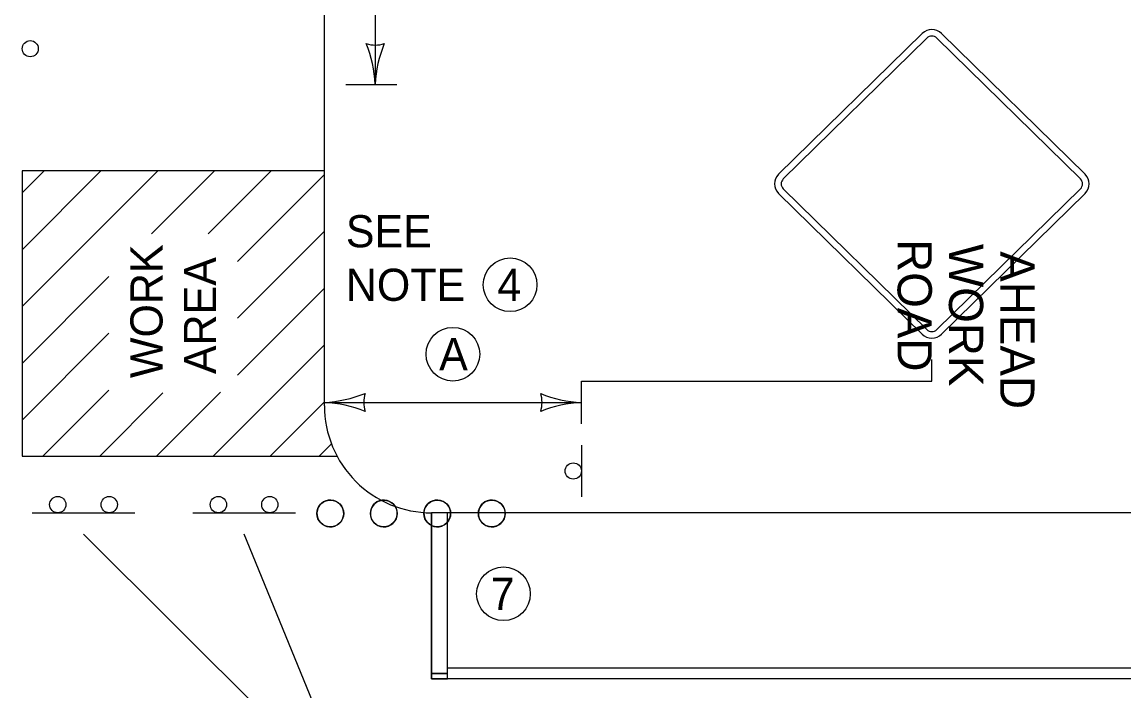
# Model space of a CAD drawing. Extents: x 49991.4 to 50021, y 49987.6 to 50011.4.
# Drawn here: x 50001.903 to 50003.961, y 49993.408 to 49994.657 of the extents above; entities that cross this region are included whole.
import ezdxf

# ---------------------------------------------------------------- set-up
doc = ezdxf.new("R2010")
doc.units = 0
for name, color, linetype in [('Level 1', 7, 'Continuous'), ('Level 2', 7, 'Continuous'), ('Level 3', 7, 'Continuous')]:
    doc.layers.add(name, color=color, linetype=linetype)

# ---------------------------------------------------------------- blocks, each defined once
blk = doc.blocks.new('ARR')
at = {"layer": 'Level 3'}
for centre, radius, start, end in [((1.53, 37.02), 37.05, 247.456, 267.6395), ((-21.37, 0), 9.13, 342.1388, 17.8612), ((1.92, -38.79), 38.83, 92.8273, 112.0772)]:
    blk.add_arc(centre, radius, start, end, dxfattribs=at)

msp = doc.modelspace()

# ---------------------------------------------------------------- linework, layer by layer
at = {"layer": 'Level 1'}
for p, q in [((50002.4673, 49993.9404), (50002.4673, 49996.0633)), ((50003.3156, 49994.3726), (50003.5839, 49994.6354)), ((50003.6198, 49994.6354), (50003.888, 49994.3726)), ((50003.3242, 49994.3638), (50003.5925, 49994.6266)), ((50003.6112, 49994.6266), (50003.8794, 49994.3638)), ((50002.4673, 49994.3789), (50001.9025, 49994.3789)), ((50001.9025, 49994.3789), (50001.9025, 49993.8464)), ((50001.9025, 49994.3377), (50001.9438, 49994.3789)), ((50001.9025, 49994.2316), (50002.0498, 49994.3789)), ((50001.9025, 49994.1255), (50002.1559, 49994.3789)), ((50002.1441, 49994.2611), (50002.262, 49994.3789)), ((50002.2502, 49994.2611), (50002.368, 49994.3789)), ((50002.3049, 49994.2097), (50002.4673, 49994.3721)), ((50003.5925, 49994.0826), (50003.3242, 49994.3454)), ((50003.8794, 49994.3454), (50003.6112, 49994.0826)), ((50003.5839, 49994.0738), (50003.3156, 49994.3366)), ((50003.888, 49994.3366), (50003.6198, 49994.0738)), ((50002.3049, 49994.1037), (50002.4673, 49994.2661)), ((50001.9025, 49994.0195), (50002.0649, 49994.1819)), ((50002.3049, 49993.9976), (50002.4673, 49994.16)), ((50001.9025, 49993.9134), (50002.0649, 49994.0758)), ((50002.2598, 49993.8464), (50002.4673, 49994.0539)), ((50001.9416, 49993.8464), (50002.0649, 49993.9697)), ((50002.0477, 49993.8464), (50002.1655, 49993.9643)), ((50002.1537, 49993.8464), (50002.2732, 49993.9659)), ((50002.3659, 49993.8464), (50002.4673, 49993.9479)), ((50002.4578, 49993.8464), (50002.4804, 49993.8691)), ((50002.9473, 49993.8665), (50002.9473, 49993.7705)), ((50001.9025, 49993.8464), (50002.4908, 49993.8464)), ((50001.9213, 49993.7405), (50002.0173, 49993.7405)), ((50002.0173, 49993.7405), (50002.1133, 49993.7405)), ((50002.2213, 49993.7405), (50002.3173, 49993.7405)), ((50002.3173, 49993.7405), (50002.4133, 49993.7405)), ((50004.4673, 49993.7404), (50002.6673, 49993.7404)), ((50002.6673, 49993.4304), (50002.6673, 49993.7404)), ((50002.6973, 49993.4304), (50002.6973, 49993.7404)), ((50002.6973, 49993.4405), (50002.6673, 49993.4405)), ((50004.4673, 49993.4504), (50002.6973, 49993.4504)), ((50004.4673, 49993.4304), (50002.6673, 49993.4304))]:
    msp.add_line(p, q, dxfattribs=at)
for points in [[(50002.6973, 49993.7404), (50002.6673, 49993.7404), (50002.6673, 49993.4405), (50002.6973, 49993.4405), (50002.6973, 49993.7404)], [(50002.6673, 49993.4405), (50002.6673, 49993.4304), (50002.6973, 49993.4304), (50002.6973, 49993.4405), (50002.6673, 49993.4405)]]:
    msp.add_lwpolyline(points, dxfattribs=at)
for centre, radius in [((50001.9179, 49994.607), 0.015), ((50002.9321, 49993.8185), 0.0152), ((50001.9693, 49993.7557), 0.0152), ((50002.0653, 49993.7557), 0.0152), ((50002.2693, 49993.7557), 0.0152), ((50002.3653, 49993.7557), 0.0152), ((50002.4783, 49993.7392), 0.025), ((50002.5782, 49993.7392), 0.025), ((50002.6781, 49993.7392), 0.025), ((50002.7799, 49993.7392), 0.025)]:
    msp.add_circle(centre, radius, dxfattribs=at)
for centre, radius, start, end in [((50002.6673, 49993.9404), 0.2, 180, 270.0006), ((50002.4783, 49993.7392), 0.025, 357.0759, 177.0759), ((50002.5782, 49993.7392), 0.025, 357.0759, 177.0759), ((50002.6781, 49993.7392), 0.025, 357.0759, 177.0759), ((50002.7799, 49993.7392), 0.025, 357.0759, 177.0759), ((50002.4783, 49993.7392), 0.025, 177.0759, 357.0759), ((50002.5782, 49993.7392), 0.025, 177.0759, 357.0759), ((50002.6781, 49993.7392), 0.025, 177.0759, 357.0759), ((50002.7799, 49993.7392), 0.025, 177.0759, 357.0759)]:
    msp.add_arc(centre, radius, start, end, dxfattribs=at)
for centre, major_axis, ratio, start_param, end_param in [((50003.6019, 49994.6175), (-0.0255, 0), 0.98963, 3.926991, 5.497787), ((50003.6019, 49994.6175), (-0.0132, 0), 0.98, 3.926991, 5.497787), ((50003.3337, 49994.3546), (-0.0255, 0), 0.98963, 5.497787, 7.068583), ((50003.8701, 49994.3546), (0.0255, 0), 0.98963, 5.497795, 7.068583), ((50003.3337, 49994.3546), (-0.0132, 0), 0.98, 5.497787, 7.068583), ((50003.8701, 49994.3546), (0.0132, 0), 0.98, 5.497795, 7.068583), ((50003.6019, 49994.0918), (-0.0132, 0), 0.98, 0.785394, 2.356194), ((50003.6019, 49994.0918), (-0.0255, 0), 0.98963, 0.785394, 2.356194)]:
    msp.add_ellipse(centre, major_axis=major_axis, ratio=ratio, start_param=start_param, end_param=end_param, dxfattribs=at)
at = {"layer": 'Level 2'}
for centre in [(50002.8142, 49994.1662), (50002.7073, 49994.0366), (50002.8017, 49993.5892)]:
    msp.add_circle(centre, 0.0501, dxfattribs=at)
at = {"layer": 'Level 3'}
for p, q in [((50002.5623, 49995.2104), (50002.5623, 49994.5404)), ((50002.5073, 49994.5404), (50002.6023, 49994.5404)), ((50002.9473, 49993.9065), (50002.9473, 49993.9865)), ((50002.4673, 49993.9465), (50002.9473, 49993.9465)), ((50002.5242, 49993.1959), (50002.0173, 49993.7005)), ((50002.5242, 49993.1959), (50002.3173, 49993.7005))]:
    msp.add_line(p, q, dxfattribs=at)
msp.add_lwpolyline([(50002.9473, 49993.9865), (50003.6019, 49993.9865), (50003.6019, 49994.0265)], dxfattribs=at)

# ---------------------------------------------------------------- block references
at = {"layer": 'Level 2', "xscale": 0.006, "yscale": 0.006}
for p, rotation in [((50002.4673, 49993.9465), -179.9999999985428), ((50002.9473, 49993.9465), 1.457212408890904e-09)]:
    msp.add_blockref('ARR', p, dxfattribs=dict(at, rotation=rotation))
at = {"layer": 'Level 3', "xscale": 0.006, "yscale": 0.006, "rotation": -90}
msp.add_blockref('ARR', (50002.5623, 49994.5404), dxfattribs=at)

# ---------------------------------------------------------------- texts
at = {"layer": 'Level 1'}
for s, p in [('ROAD', (50003.5379, 49994.2514)), ('WORK', (50003.6338, 49994.2424)), ('AHEAD', (50003.7297, 49994.2288))]:
    msp.add_text(s, height=0.06395, rotation=270, dxfattribs=at).set_placement(p)
at = {"layer": 'Level 2'}
for s, p in [('SEE', (50002.5073, 49994.2362)), ('NOTE', (50002.5073, 49994.1362)), ('4', (50002.7903, 49994.1362)), ('7', (50002.7779, 49993.5592))]:
    msp.add_text(s, height=0.06, dxfattribs=at).set_placement(p)
for s, rotation, p in [('WORK', 90, (50002.1649, 49993.992)), ('AREA', 90, (50002.2649, 49993.9994)), ('A', 0, (50002.6816, 49994.0066))]:
    msp.add_text(s, height=0.06, rotation=rotation, dxfattribs=at).set_placement(p)

doc.saveas('drawing.dxf')
